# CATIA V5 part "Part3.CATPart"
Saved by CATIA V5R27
Part number: Part3
Bounding box of the stored display mesh (mm): x -13.389 to 13.389, y -37 to 11, z 255.111 to 281.889
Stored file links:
  E:\university\my-thesis\My Thesis Publication\Final-Updata\CAD\Part3.CATPart
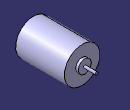
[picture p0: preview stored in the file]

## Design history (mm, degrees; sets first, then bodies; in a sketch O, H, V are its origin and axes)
Set1
  Sketch1 on yz-plane, origin (0, 0, 0), H (0, 1, 0), V (0, 0, 1)
    line L1 (-37, 268.5) -> (-37, 255)
    line L2 (-37, 255) -> (0, 255)
    line L3 (0, 255) -> (0, 263.5)
    line L4 (0, 263.5) -> (2, 263.5)
    point P5 (2, 263.5)
    line L5 (2, 263.5) -> (2, 267.5)
    line L6 (2, 267.5) -> (11, 267.5)
    line L7 (11, 267.5) -> (11, 268.5)
    line L8 (11, 268.5) -> (-37, 268.5)
    projected line E1 (3, 273.5) -> (3, 263.5) from edge of DatumCurve1
    point P10 (3, 263.5)
    distance P5 P10 V = 0
    length L4 = 2
    length L2 = 37
    length L6 = 9
    length L1 = 13.5
    length L7 = 1
    length L5 = 4
    distance L3 E1 = 3
    vertical: L1 V, L3 V, L5 V, L7 V
    horizontal: L2 H, L4 H, L6 H, L8 H
  DatumCurve1
Body1 (main body)
  Shaft1: profile Sketch1, axis Sketch1.L8, angle 360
